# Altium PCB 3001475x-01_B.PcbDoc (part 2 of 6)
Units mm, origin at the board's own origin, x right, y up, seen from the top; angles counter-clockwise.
Board outline 335 x 91 mm, 12 copper layers (Top Layer, L2 GND, Layer 3, L4 GND, Layer 5, L6 PWR, L7 3V3, Layer 8, L9 GND, Layer 10, L11 GND, Bottom Layer), stack 1.59 mm thick; 339 components, 431 nets, 1732 pads, 1526 vias.
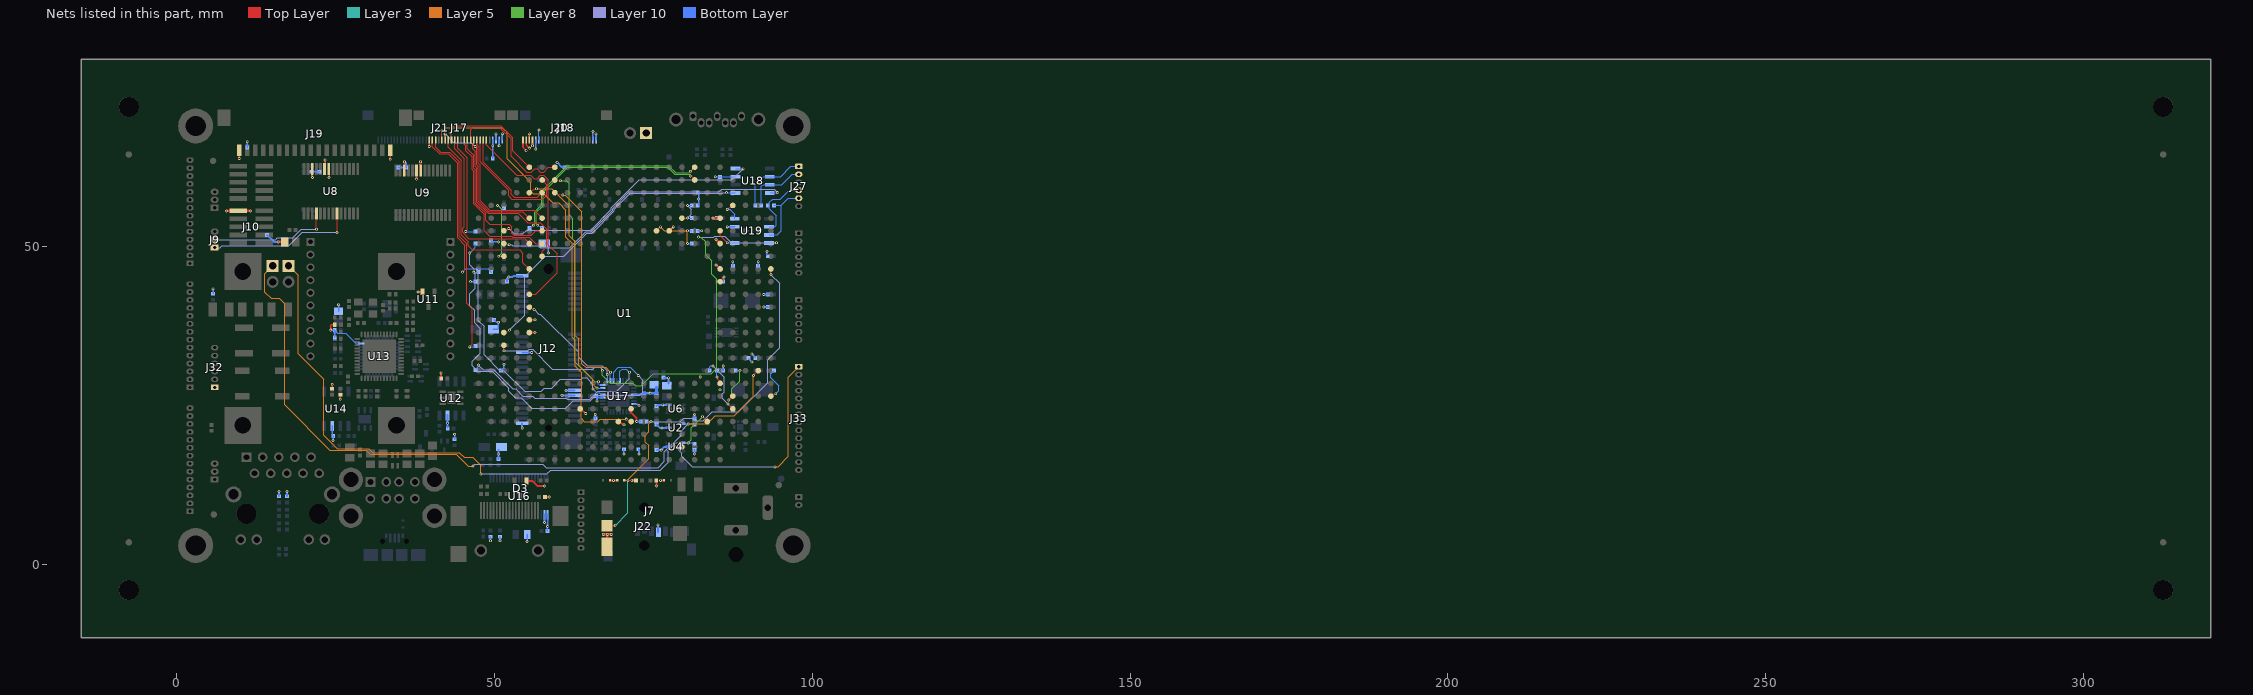
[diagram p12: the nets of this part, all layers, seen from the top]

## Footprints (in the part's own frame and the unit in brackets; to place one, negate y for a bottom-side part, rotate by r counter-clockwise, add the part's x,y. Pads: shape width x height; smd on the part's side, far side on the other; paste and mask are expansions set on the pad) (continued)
MODULE_CCWMX6 [mil]
  round 35 smd: A5(-590.55,905.51) A6(-511.81,905.51) A7(-433.07,905.51) A8(-354.33,905.51) A9(-275.59,905.51) A10(-196.85,905.51) A11(-118.11,905.51) A12(-39.37,905.51) A13(39.37,905.51) A14(118.11,905.51) A15(196.85,905.51) A16(275.59,905.51) A17(354.33,905.51) A18(433.07,905.51) A19(511.81,905.51) A20(590.55,905.51) AA2(-826.77,-669.29) AA3(-748.03,-669.29) AA4(-669.29,-669.29) AA5(-590.55,-669.29) AA6(-511.81,-669.29) AA7(-433.07,-669.29) AA8(-354.33,-669.29) AA9(-275.59,-669.29) AA10(-196.85,-669.29) AA11(-118.11,-669.29) AA12(-39.37,-669.29) AA13(39.37,-669.29) AA14(118.11,-669.29) AA15(196.85,-669.29) AA16(275.59,-669.29) AA17(354.33,-669.29) AA18(433.07,-669.29) AA19(511.81,-669.29) AA20(590.55,-669.29) AA21(669.29,-669.29) AA22(748.03,-669.29) AA23(826.77,-669.29) AB3(-748.03,-748.03) AB4(-669.29,-748.03) AB5(-590.55,-748.03) AB6(-511.81,-748.03) AB7(-433.07,-748.03) AB8(-354.33,-748.03) AB9(-275.59,-748.03) AB10(-196.85,-748.03) AB11(-118.11,-748.03) AB12(-39.37,-748.03) AB13(39.37,-748.03) AB14(118.11,-748.03) AB15(196.85,-748.03) AB16(275.59,-748.03) AB17(354.33,-748.03) AB18(433.07,-748.03) AB19(511.81,-748.03) AB20(590.55,-748.03) AB21(669.29,-748.03) AB22(748.03,-748.03) AC4(-669.29,-826.77) AC5(-590.55,-826.77) AC6(-511.81,-826.77) AC7(-433.07,-826.77) AC8(-354.33,-826.77) AC9(-275.59,-826.77) AC10(-196.85,-826.77) AC11(-118.11,-826.77) AC12(-39.37,-826.77) AC13(39.37,-826.77) AC14(118.11,-826.77) AC15(196.85,-826.77) AC16(275.59,-826.77) AC17(354.33,-826.77) AC18(433.07,-826.77) AC19(511.81,-826.77) AC20(590.55,-826.77) AC21(669.29,-826.77) AD5(-590.55,-905.51) AD6(-511.81,-905.51) AD7(-433.07,-905.51) AD8(-354.33,-905.51) AD9(-275.59,-905.51) AD10(-196.85,-905.51) AD11(-118.11,-905.51) AD12(-39.37,-905.51) AD13(39.37,-905.51) AD14(118.11,-905.51) AD15(196.85,-905.51) AD16(275.59,-905.51) AD17(354.33,-905.51) AD18(433.07,-905.51) AD19(511.81,-905.51) AD20(590.55,-905.51) B4(-669.29,826.77) B5(-590.55,826.77) B6(-511.81,826.77) B7(-433.07,826.77) B8(-354.33,826.77) B9(-275.59,826.77) B10(-196.85,826.77) B11(-118.11,826.77) B12(-39.37,826.77) B13(39.37,826.77) B14(118.11,826.77) B15(196.85,826.77) B16(275.59,826.77) B17(354.33,826.77) B18(433.07,826.77) B19(511.81,826.77) B20(590.55,826.77) B21(669.29,826.77) C3(-748.03,748.03) C4(-669.29,748.03) C5(-590.55,748.03) C6(-511.81,748.03) C7(-433.07,748.03) C8(-354.33,748.03) C9(-275.59,748.03) C10(-196.85,748.03) C11(-118.11,748.03) C12(-39.37,748.03) C13(39.37,748.03) C14(118.11,748.03) C15(196.85,748.03) C16(275.59,748.03) C17(354.33,748.03) C18(433.07,748.03) C19(511.81,748.03) C20(590.55,748.03) C21(669.29,748.03) C22(748.03,748.03) D2(-826.77,669.29) D3(-748.03,669.29) D4(-669.29,669.29) D5(-590.55,669.29) D6(-511.81,669.29) D7(-433.07,669.29) D8(-354.33,669.29) D9(-275.59,669.29) D10(-196.85,669.29) D11(-118.11,669.29) D12(-39.37,669.29) D13(39.37,669.29) D14(118.11,669.29) D15(196.85,669.29) D16(275.59,669.29) D17(354.33,669.29) D18(433.07,669.29) D19(511.81,669.29) D20(590.55,669.29) D21(669.29,669.29) D22(748.03,669.29) D23(826.77,669.29) E1(-905.51,590.55) E2(-826.77,590.55) E3(-748.03,590.55) E4(-669.29,590.55) E5(-590.55,590.55) E6(-511.81,590.55) E7(-433.07,590.55) E8(-354.33,590.55) E9(-275.59,590.55) E10(-196.85,590.55) E11(-118.11,590.55) E12(-39.37,590.55) E13(39.37,590.55) E14(118.11,590.55) E15(196.85,590.55) E16(275.59,590.55) E17(354.33,590.55) E18(433.07,590.55) E19(511.81,590.55) E20(590.55,590.55) E21(669.29,590.55) E22(748.03,590.55) E23(826.77,590.55) E24(905.51,590.55) F1(-905.51,511.81) F2(-826.77,511.81) F3(-748.03,511.81) F4(-669.29,511.81) F5(-590.55,511.81) F6(-511.81,511.81) F7(-433.07,511.81) F8(-354.33,511.81) F9(-275.59,511.81) F10(-196.85,511.81) F11(-118.11,511.81) F12(-39.37,511.81) F13(39.37,511.81) F14(118.11,511.81) F15(196.85,511.81) F16(275.59,511.81) F17(354.33,511.81) F18(433.07,511.81) F19(511.81,511.81) F20(590.55,511.81) F21(669.29,511.81) F22(748.03,511.81) F23(826.77,511.81) F24(905.51,511.81) G1(-905.51,433.07) G2(-826.77,433.07) G3(-748.03,433.07) G4(-669.29,433.07) G5(-590.55,433.07) G6(-511.81,433.07) G7(-433.07,433.07) G8(-354.33,433.07) G9(-275.59,433.07) G10(-196.85,433.07) G11(-118.11,433.07) G12(-39.37,433.07) G13(39.37,433.07) G14(118.11,433.07) G15(196.85,433.07) G16(275.59,433.07) G17(354.33,433.07) G18(433.07,433.07) G19(511.81,433.07) G20(590.55,433.07) G21(669.29,433.07) G22(748.03,433.07) G23(826.77,433.07) G24(905.51,433.07) H1(-905.51,354.33) H2(-826.77,354.33) H3(-748.03,354.33) H4(-669.29,354.33) H5(-590.55,354.33) H6(-511.81,354.33) H19(511.81,354.33) H20(590.55,354.33) H21(669.29,354.33) H22(748.03,354.33) H23(826.77,354.33) H24(905.51,354.33) J1(-905.51,275.59) J2(-826.77,275.59) J3(-748.03,275.59) J4(-669.29,275.59) J5(-590.55,275.59) J20(590.55,275.59) J21(669.29,275.59) J22(748.03,275.59) J23(826.77,275.59) J24(905.51,275.59) K1(-905.51,196.85) K2(-826.77,196.85) K3(-748.03,196.85) K4(-669.29,196.85) K5(-590.55,196.85) K20(590.55,196.85) K21(669.29,196.85) K22(748.03,196.85) K23(826.77,196.85) K24(905.51,196.85) L1(-905.51,118.11) L2(-826.77,118.11) L3(-748.03,118.11) L4(-669.29,118.11) L5(-590.55,118.11) L20(590.55,118.11) L21(669.29,118.11) L22(748.03,118.11) L23(826.77,118.11) L24(905.51,118.11) M1(-905.51,39.37) M2(-826.77,39.37) M3(-748.03,39.37) M4(-669.29,39.37) M5(-590.55,39.37) M20(590.55,39.37) M21(669.29,39.37) M22(748.03,39.37) M23(826.77,39.37) M24(905.51,39.37) N1(-905.51,-39.37) N2(-826.77,-39.37) N3(-748.03,-39.37) N4(-669.29,-39.37) N5(-590.55,-39.37) N20(590.55,-39.37) N21(669.29,-39.37) N22(748.03,-39.37) N23(826.77,-39.37) N24(905.51,-39.37) P1(-905.51,-118.11) P2(-826.77,-118.11) P3(-748.03,-118.11) P4(-669.29,-118.11) P5(-590.55,-118.11) P20(590.55,-118.11) P21(669.29,-118.11) P22(748.03,-118.11) P23(826.77,-118.11) P24(905.51,-118.11) R1(-905.51,-196.85) R2(-826.77,-196.85) R3(-748.03,-196.85) R4(-669.29,-196.85) R5(-590.55,-196.85) R20(590.55,-196.85) R21(669.29,-196.85) R22(748.03,-196.85) R23(826.77,-196.85) R24(905.51,-196.85) T1(-905.51,-275.59) T2(-826.77,-275.59) T3(-748.03,-275.59) T4(-669.29,-275.59) T5(-590.55,-275.59) T20(590.55,-275.59) T21(669.29,-275.59) T22(748.03,-275.59) T23(826.77,-275.59) T24(905.51,-275.59) U1(-905.51,-354.33) U2(-826.77,-354.33) U3(-748.03,-354.33) U4(-669.29,-354.33) U5(-590.55,-354.33) U6(-511.81,-354.33) U19(511.81,-354.33) U20(590.55,-354.33) U21(669.29,-354.33) U22(748.03,-354.33) U23(826.77,-354.33) U24(905.51,-354.33) V1(-905.51,-433.07) V2(-826.77,-433.07) V3(-748.03,-433.07) V4(-669.29,-433.07) V5(-590.55,-433.07) V6(-511.81,-433.07) V7(-433.07,-433.07) V8(-354.33,-433.07) V9(-275.59,-433.07) V10(-196.85,-433.07) V11(-118.11,-433.07) V12(-39.37,-433.07) V13(39.37,-433.07) V14(118.11,-433.07) V15(196.85,-433.07) V16(275.59,-433.07) V17(354.33,-433.07) V18(433.07,-433.07) V19(511.81,-433.07) V20(590.55,-433.07) V21(669.29,-433.07) V22(748.03,-433.07) V23(826.77,-433.07) V24(905.51,-433.07) W1(-905.51,-511.81) W2(-826.77,-511.81) W3(-748.03,-511.81) W4(-669.29,-511.81) W5(-590.55,-511.81) W6(-511.81,-511.81) W7(-433.07,-511.81) W8(-354.33,-511.81) W9(-275.59,-511.81) W10(-196.85,-511.81) W11(-118.11,-511.81) W12(-39.37,-511.81) W13(39.37,-511.81) W14(118.11,-511.81) W15(196.85,-511.81) W16(275.59,-511.81) W17(354.33,-511.81) W18(433.07,-511.81) W19(511.81,-511.81) W20(590.55,-511.81) W21(669.29,-511.81) W22(748.03,-511.81) W23(826.77,-511.81) W24(905.51,-511.81) Y1(-905.51,-590.55) Y2(-826.77,-590.55) Y3(-748.03,-590.55) Y4(-669.29,-590.55) Y5(-590.55,-590.55) Y6(-511.81,-590.55) Y7(-433.07,-590.55) Y8(-354.33,-590.55) Y9(-275.59,-590.55) Y10(-196.85,-590.55) Y11(-118.11,-590.55) Y12(-39.37,-590.55) Y13(39.37,-590.55) Y14(118.11,-590.55) Y15(196.85,-590.55) Y16(275.59,-590.55) Y17(354.33,-590.55) Y18(433.07,-590.55) Y19(511.81,-590.55) Y20(590.55,-590.55) Y21(669.29,-590.55) Y22(748.03,-590.55) Y23(826.77,-590.55) Y24(905.51,-590.55)
  body extent -984,-984 984,984, height 220
MOLEX_53047-0210 [mm]
  rrect20% 0.875x1.125 hole 0.5: 1(0,0)
  oval 0.875x1.15 hole 0.5: 2(1.25,0)
  body extent -1.52,-1.15 2.73,2.05, height 4.2
MOLEX_53047-0310 [mm]
  rect 1x1.25 hole 0.5: 1(0,0)
  oval 1x1.25 hole 0.5: 2(1.25,0) 3(2.5,0)
  body extent -1.5,-1.15 4,2.05, height 4.2
MOLEX_53047-0610#1 [mm]
  rrect20% 0.875x1.125 hole 0.5: 1(0,0)
  oval 0.875x1.15 hole 0.5: 2(1.25,0) 3(2.5,0) 4(3.75,0) 5(5,0) 6(6.25,0)
  body extent -1.5,-1.15 7.75,2.05, height 4.2
MOLEX_53047-0610#2 [mm]
  rect 0.875x1.15 hole 0.5: 1(0,0)
  oval 0.875x1.15 hole 0.5: 2(1.25,0) 3(2.5,0) 4(3.75,0) 5(5,0) 6(6.25,0)
  body extent -1.5,-1.15 7.75,2.05, height 4.2
MOLEX_53047-0810 [mm]
  rect 0.875x1.15 hole 0.5: 1(0,0)
  oval 0.875x1.15 hole 0.5: 2(1.25,0) 3(2.5,0) 4(3.75,0) 5(5,0) 6(6.25,0) 7(7.5,0) 8(8.75,0)
  body extent -1.5,-1.15 10.25,2.05, height 4.2
MOLEX_53047-1410 [mm]
  rrect20% 0.875x1.125 hole 0.5: 1(0,0)
  oval 0.875x1.15 hole 0.5: 2(1.25,0) 3(2.5,0) 4(3.75,0) 5(5,0) 6(6.25,0) 7(7.5,0) 8(8.75,0) 9(10,0) 10(11.25,0) 11(12.5,0) 12(13.75,0) 13(15,0) 14(16.25,0)
  body extent -1.5,-1.15 17.75,2.05, height 4.2
MOLEX_78727-0001 [mm]
  rect 0.8x0.6 smd: 1(0.33,4.38) 2(0.33,1.84) 3(0.33,-0.7) 4(0.33,-3.24) 5(-7.29,4.38) 6(-7.29,1.84) 7(-7.29,-0.7) 8(-7.29,-3.24)
  rect 0.85x0.8 smd: 9(-13.99,-4.98)
  rect 1.5x0.42 smd: 10(-2.47,-6.54) 12(-6.35,7.11) 13(-12.21,7.11) 14(-12.21,-7.11) 15(-6.35,-7.11)
  rect 1.4x0.87 smd: 11(0,6.95) 16(0,-6.95)
  body extent -14.53,-7.26 0.69,7.27, height 1.4
MOLEX_500873-0806 [mm]
  rect 0.8x1.5 smd: 1(0,0) 2(1.1,-0.4) 3(2.2,0) 4(3.3,0.2) 5(4.4,0) 6(5.5,0.2) 7(6.6,0) 8(7.7,0)
  rect 1.8x1.4 smd: 9(1.2,-10.3) 10(6.9,-10.3)
  rect 1.4x1.9 smd: 11(8.5,2.85) 12(-4.65,3.85)
  Top Layer keep-out region: 8.6,1.75 9.2,1.75 9.2,-11 8.6,-11
  body extent -5.05,-10.7 8.95,4.5, height 1.87
omron_xf2m-2015-1a [mm]
  rect 0.25x1.1 smd: 1(-4.75,1.95) 2(-4.25,1.95) 3(-3.75,1.95) 4(-3.25,1.95) 5(-2.75,1.95) 6(-2.25,1.95) 7(-1.75,1.95) 8(-1.25,1.95) 9(-0.75,1.95) 10(-0.25,1.95) 11(0.25,1.95) 12(0.75,1.95) 13(1.25,1.95) 14(1.75,1.95) 15(2.25,1.95) 16(2.75,1.95) 17(3.25,1.95) 18(3.75,1.95) 19(4.25,1.95) 20(4.75,1.95)
  rect 1.7x1.5 smd: M1(6.4,-1.95) M2(-6.4,-1.95)
  body extent -7.05,-2.9 7.05,3.3, height 2.18
OMRON_XF2M-2415-1A [mm]
  rect 0.25x1.1 smd: 1(-5.75,1.95) 2(-5.25,1.95) 3(-4.75,1.95) 4(-4.25,1.95) 5(-3.75,1.95) 6(-3.25,1.95) 7(-2.75,1.95) 8(-2.25,1.95) 9(-1.75,1.95) 10(-1.25,1.95) 11(-0.75,1.95) 12(-0.25,1.95) 13(0.25,1.95) 14(0.75,1.95) 15(1.25,1.95) 16(1.75,1.95) 17(2.25,1.95) 18(2.75,1.95) 19(3.25,1.95) 20(3.75,1.95) 21(4.25,1.95) 22(4.75,1.95) 23(5.25,1.95) 24(5.75,1.95)
  rect 1.7x1.5 smd: M1(7.4,-1.95) M2(-7.4,-1.95)
  body extent -8.05,-3.55 8.05,2.65, height 3.2
OMRON_XF2M-4015-1A [mm]
  rect 0.25x1.1 smd: 1(-9.75,1.95) 2(-9.25,1.95) 3(-8.75,1.95) 4(-8.25,1.95) 5(-7.75,1.95) 6(-7.25,1.95) 7(-6.75,1.95) 8(-6.25,1.95) 9(-5.75,1.95) 10(-5.25,1.95) 11(-4.75,1.95) 12(-4.25,1.95) 13(-3.75,1.95) 14(-3.25,1.95) 15(-2.75,1.95) 16(-2.25,1.95) 17(-1.75,1.95) 18(-1.25,1.95) 19(-0.75,1.95) 20(-0.25,1.95) 21(0.25,1.95) 22(0.75,1.95) 23(1.25,1.95) 24(1.75,1.95) 25(2.25,1.95) 26(2.75,1.95) 27(3.25,1.95) 28(3.75,1.95) 29(4.25,1.95) 30(4.75,1.95) 31(5.25,1.95) 32(5.75,1.95) 33(6.25,1.95) 34(6.75,1.95) 35(7.25,1.95) 36(7.75,1.95) 37(8.25,1.95) 38(8.75,1.95) 39(9.25,1.95) 40(9.75,1.95)
  rect 1.7x1.5 smd: M1(11.4,-1.95) M2(-11.4,-1.95)
  body extent -12.05,-2.9 12.05,3.3, height 2.18
OSC210P320X250X90-4N [mm]
  rect 1.3x1.1 smd: 1(-1.15,-0.95) 2(1.15,-0.95) 3(1.15,0.95) 4(-1.15,0.95)
  body extent -1.63,-1.3 1.62,1.3, height 0.6
QFN50P500X500X100-33CN [mm]
  rrect50% 0.85x0.3 smd: 1(-2.45,1.75) 2(-2.45,1.25) 3(-2.45,0.75) 4(-2.45,0.25) 5(-2.45,-0.25) 6(-2.45,-0.75) 7(-2.45,-1.25) 8(-2.45,-1.75) 17(2.45,-1.75) 18(2.45,-1.25) 19(2.45,-0.75) 20(2.45,-0.25) 21(2.45,0.25) 22(2.45,0.75) 23(2.45,1.25) 24(2.45,1.75)
  rrect50% 0.3x0.85 smd: 9(-1.75,-2.45) 10(-1.25,-2.45) 11(-0.75,-2.45) 12(-0.25,-2.45) 13(0.25,-2.45) 14(0.75,-2.45) 15(1.25,-2.45) 16(1.75,-2.45) 25(1.75,2.45) 26(1.25,2.45) 27(0.75,2.45) 28(0.25,2.45) 29(-0.25,2.45) 30(-0.75,2.45) 31(-1.25,2.45) 32(-1.75,2.45)
  rect 3.45x3.45 smd: 33(0,0)
  body extent -2.5,-2.5 2.5,2.5, height 1.01
QFN50P600X600X100-37AN [mm]
  rrect35% 1.05x0.3 smd: 1(-2.8,2) 9(-2.8,-2) 19(2.8,-2) 27(2.8,2)
  rrect25% 1.1x0.3 smd: 2(-2.8,1.5) 3(-2.8,1) 4(-2.8,0.5) 5(-2.8,0) 6(-2.8,-0.5) 7(-2.8,-1) 8(-2.8,-1.5) 20(2.8,-1.5) 21(2.8,-1) 22(2.8,-0.5) 23(2.8,0) 24(2.8,0.5) 25(2.8,1) 26(2.8,1.5)
  rrect35% 0.3x1.05 smd: 10(-2,-2.8) 18(2,-2.8) 28(2,2.8) 36(-2,2.8)
  rrect25% 0.3x1.1 smd: 11(-1.5,-2.8) 12(-1,-2.8) 13(-0.5,-2.8) 14(0,-2.8) 15(0.5,-2.8) 16(1,-2.8) 17(1.5,-2.8) 29(1.5,2.8) 30(1,2.8) 31(0.5,2.8) 32(0,2.8) 33(-0.5,2.8) 34(-1,2.8) 35(-1.5,2.8)
  rect 3.8x3.8 smd: 37(0,0)
  body extent -3.05,-3.05 3.05,3.05, height 1.01
QFN50P700X700X100-49N [mm]
  oval 0.9x0.3 smd: 1(-3.45,2.75) 2(-3.45,2.25) 3(-3.45,1.75) 4(-3.45,1.25) 5(-3.45,0.75) 6(-3.45,0.25) 7(-3.45,-0.25) 8(-3.45,-0.75) 9(-3.45,-1.25) 10(-3.45,-1.75) 11(-3.45,-2.25) 12(-3.45,-2.75) 25(3.45,-2.75) 26(3.45,-2.25) 27(3.45,-1.75) 28(3.45,-1.25) 29(3.45,-0.75) 30(3.45,-0.25) 31(3.45,0.25) 32(3.45,0.75) 33(3.45,1.25) 34(3.45,1.75) 35(3.45,2.25) 36(3.45,2.75)
  oval 0.3x0.9 smd: 13(-2.75,-3.45) 14(-2.25,-3.45) 15(-1.75,-3.45) 16(-1.25,-3.45) 17(-0.75,-3.45) 18(-0.25,-3.45) 19(0.25,-3.45) 20(0.75,-3.45) 21(1.25,-3.45) 22(1.75,-3.45) 23(2.25,-3.45) 24(2.75,-3.45) 37(2.75,3.45) 38(2.25,3.45) 39(1.75,3.45) 40(1.25,3.45) 41(0.75,3.45) 42(0.25,3.45) 43(-0.25,3.45) 44(-0.75,3.45) 45(-1.25,3.45) 46(-1.75,3.45) 47(-2.25,3.45) 48(-2.75,3.45)
  rect 5.3x5.3 smd: 49(0,0)
  body extent -3.57,-3.57 3.57,3.57, height 1.01
RESC1005X40N [mm]
  rect 0.57x0.62 smd: 1(-0.48,0) 2(0.48,0)
  body extent -0.5,-0.25 0.5,0.25, height 0.4
RESC1609X55N [mm]
  rect 0.9x1 smd: 1(-0.8,0) 2(0.8,0)
  body extent -0.87,-0.48 0.87,0.48, height 0.55
SAMTEC_FTSH-105-01-F-DV [mil]
  rect 110x29 smd: 1(-80,100) 2(80,100) 3(-80,50) 4(80,50) 5(-80,0) 6(80,0) 7(-80,-50) 8(80,-50) 9(-80,-100) 10(80,-100)
  body extent -115,-125 115,125, height 234
SAMTEC_MMS-110-01-L-SV [mil]
  rect 50x50 hole 28: 1(0,0)
  round 50 hole 28: 2(78.74,0) 3(157.48,0) 4(236.22,0) 5(314.96,0) 6(393.7,0) 7(472.44,0) 8(551.18,0) 9(629.92,0) 10(708.66,0)
  body extent -44,-39 753,39, height 175
SODFL1006X43N12 [mm]
  rect 0.32x0.43 smd: 1(-0.55,0) 2(0.55,0)
  body extent -0.58,-0.33 0.58,0.33, height 0.4
SOIC127P600X175-8N [mm]
  rect 0.6x1.55 smd: 1(-1.905,-2.7) 2(-0.635,-2.7) 3(0.635,-2.7) 4(1.905,-2.7) 5(1.905,2.7) 6(0.635,2.7) 7(-0.635,2.7) 8(-1.905,2.7)
  body extent -2.5,-3.1 2.5,3.1, height 1.75
SON45P300X200X80_175X145E-9AN [mm] "DFN8 with D shape pads - 1.75mm x 1.45mm E-pad"
  rrect100% 0.8x0.25 smd paste-0.03: 1(-1.5,0.675) 2(-1.5,0.225) 3(-1.5,-0.225) 4(-1.5,-0.675) 5(1.5,-0.675) 6(1.5,-0.225) 7(1.5,0.225) 8(1.5,0.675)
  rect 1.75x1.45 smd: 9(0,0)
  body extent -1.5,-1 1.5,1, height 0.8
SON95P300X300X80-7N [mm]
  rect 0.4x1 smd: 1(-0.95,-1.4) 2(0,-1.4) 3(0.95,-1.4) 4(0.95,1.4) 5(0,1.4) 6(-0.95,1.4)
  rect 2x1.3 smd: 7(0,0)
  body extent -1.58,-1.58 1.58,1.58, height 0.8
SOP50P640X120-38N [mm]
  rect 1.5x0.3 smd: 1(-2.9,4.5) 2(-2.9,4) 3(-2.9,3.5) 4(-2.9,3) 5(-2.9,2.5) 6(-2.9,2) 7(-2.9,1.5) 8(-2.9,1) 9(-2.9,0.5) 10(-2.9,0) 11(-2.9,-0.5) 12(-2.9,-1) 13(-2.9,-1.5) 14(-2.9,-2) 15(-2.9,-2.5) 16(-2.9,-3) 17(-2.9,-3.5) 18(-2.9,-4) 19(-2.9,-4.5) 20(2.9,-4.5) 21(2.9,-4) 22(2.9,-3.5) 23(2.9,-3) 24(2.9,-2.5) 25(2.9,-2) 26(2.9,-1.5) 27(2.9,-1) 28(2.9,-0.5) 29(2.9,0) 30(2.9,0.5) 31(2.9,1) 32(2.9,1.5) 33(2.9,2) 34(2.9,2.5) 35(2.9,3) 36(2.9,3.5) 37(2.9,4) 38(2.9,4.5)
  body extent -3.3,-4.9 3.3,4.9, height 1.1
SOP65P780X200-28N [mm] "28-LEAD SHRINK SMALL OUTLINE  PACKAGE"
  rect 1.9x0.45 smd: 1(-3.5,4.225) 2(-3.5,3.575) 3(-3.5,2.925) 4(-3.5,2.275) 5(-3.5,1.625) 6(-3.5,0.975) 7(-3.5,0.325) 8(-3.5,-0.325) 9(-3.5,-0.975) 10(-3.5,-1.625) 11(-3.5,-2.275) 12(-3.5,-2.925) 13(-3.5,-3.575) 14(-3.5,-4.225) 15(3.5,-4.225) 16(3.5,-3.575) 17(3.5,-2.925) 18(3.5,-2.275) 19(3.5,-1.625) 20(3.5,-0.975) 21(3.5,-0.325) 22(3.5,0.325) 23(3.5,0.975) 24(3.5,1.625) 25(3.5,2.275) 26(3.5,2.925) 27(3.5,3.575) 28(3.5,4.225)
  body extent -4.1,-5.25 4.1,5.25, height 2.01
SOT65P210X110-5N [mm]
  rect 0.4x0.95 smd: 1(-0.65,-1.1) 2(0,-1.1) 3(0.65,-1.1) 4(0.65,1.1) 5(-0.65,1.1)
  body extent -1.07,-1.2 1.07,1.2, height 1.11
SOT65P210X110-6N [mm]
  rect 0.4x0.95 smd: 1(-0.65,-1.1) 2(0,-1.1) 3(0.65,-1.1) 4(0.65,1.1) 5(0,1.1) 6(-0.65,1.1)
  body extent -1.07,-1.2 1.07,1.2, height 1.11
SOT95P240X110-3N [mm]
  rect 0.7x1.1 smd: 1(-0.95,-1.2) 2(0.95,-1.2) 3(0,1.2)
  body extent -1.56,-1.35 1.56,1.35, height 1.11
SOT95P240X110_AXK-3N [mm]
  rect 0.65x1.05 smd: A(-0.95,-1.15) K(0,1.15) X(0.95,-1.15)
  body extent -1.56,-1.35 1.56,1.35, height 1.11
SOT95P240X110_GSD-3N [mm]
  rect 0.65x1.05 smd: D(0,1.15) G(-0.95,-1.15) S(0.95,-1.15)
  body extent -1.56,-1.35 1.56,1.35, height 1.11
SOTFL50P160X80_GSD-3N [mm]
  rect 0.4x0.77 smd: D(0,0.69) G(-0.5,-0.69) S(0.5,-0.69)
  body extent -0.85,-0.85 0.85,0.85, height 0.8
SW_KSC221J [mm]
  rect 1x2.8 smd: 1(2,2.9) 2(2,-2.9) 3(-2,2.9) 4(-2,-2.9)
  body extent -3.1,-3.4 3.1,3.4, height 3.5
XTAL_C3E-3427 [mm]
  rect 1.4x1.15 smd: 1(-1.1,-0.8) 2(1.1,-0.8) 3(1.1,0.8) 4(-1.1,0.8)
  body extent -1.7,-1.35 1.7,1.35, height 0.75

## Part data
C1 C34 C35 C36: library part 1001196, "CAP TANT 100UF 6.3V 20% 1206"
C2 C9 C11 C12 C42 C49 C56 C57 C60 C67 C69 C71 C72 C98: library part 1001168, "CAP CER 10UF 10V 20% X5R 0402"
C3 C18 C19 C20 C21 C22 C23 C24 C25 C26 C27 C62 C65 C87 C88 C91 C92 C93 C94: library part 1001167, "CAP CER 1UF 10V 10% X5R 0402"
C4 C5 C6 C7 C10 C13 C29 C31 C32 C33 C37 C38 C39 C41 C43 C44 C45 C46 C47 C48 C50 C51 C52 C53 C54 C55 C58 C59 C61 C66 C68 C70 C73 C74 C75 C76 C77 C78 C79 C81 C82 C83 C84 C85 C86 C89 C90 C95 C96 C97 C99 C100 C101: library part 1000006, "CAP 100nF 16V 10% X7R 0402"
C8: library part 1001164, "CAP TANT 47UF 20V 10% 2413"
C14 C15 C16 C17: library part 1001165, "CAP CER 10000PF 16V 10% X7R 0402"
C28 C30: library part 1001166, "CAP CER 22PF 50V 5% NP0 0402"
C40 C80: library part 1000500, "CAP CER 4.7UF 25V 10% X5R 0805"
C63 C64: library part 1000010, "CAP 33pF 50V 5% NP0 0402"
D1 D4: library part 1001189, "LED GREEN 573NM 1208 SMD"
D2: library part 1000824, "DIODE ZENER 5.1V 300MW SOT23-3"
D3: library part 1001169, "DIODE SCHOTTKY 30V 0.2A SOT23-3"
D5: library part 1001188, "LED YELLOW 588NM 1208 SMD"
D6: library part 1001190, "LED RED 653NM 20MA 1208 SMD"
D7 D8 D9 D10: library part 1001264, "TVS DIODE 5VWM SOD923"
FIDUCIAL1 FIDUCIAL2 FIDUCIAL3 FIDUCIAL4 FIDUCIAL5 FIDUCIAL6: library part CAD0023, "40 Mil Round Fiducial"
H1048 H1049 H1050 H1051: library part CAD0006
H1052 H1053 H1054 H1055: library part CAD0023
J1: library part 1001105, "DC Power Jack"
J2: library part 1001136, "CONN HEADER 2POS 1.25MM VERT TIN"
J3 J9 J25: library part 1001183, "CONN HEADER 3POS 1.25MM VERT TIN"
J4 J5: library part 1001128, "CONN HEADER 2POS .100\" SGL GOLD"
J6: library part 1001106, "CONN HEADER 2POS .100 VERT GOLD"
J7: library part 1001118, "CONN TRANSFLSH R/A PUSH-PUSH SMD"
J8: library part 1001115, "CONN PLUG SATA 7PS VERT PCB GOLD"
J10 J11: library part 1000034, "CONN HEADER 10POS DUAL .05\" SMD"
J12: library part 1001130, "SMCONN,MINI PCI EXP, 6.8MM HT"
J13: library part 1001142, "CONN MAGJACK 1PORT 1000 BASE-T"
J14: library part 1001120, "MEMORY CARD 6POS PUSH/PULL SMD"
J15: library part 1001121, "USB Stacked Dual A type"
J16: library part 1001117, "CONN RECEPT MICRO-USB TYPE AB R/A"
J17 J18: library part 1001145, "CONN FPC 20POS 0.5MM PITCH SMD"
J19: library part 1001132, "CONN HEADER 20POS 1.25MM R/A SMD"
J20: library part 1001182, "CONN FPC 24POS 0.5MM PITCH SMD"
J21: library part 1001144, "CONN FPC 40POS 0.5MM PITCH SMD"
J22: library part 1001133, "CONN JACK STEREO 5POS 3.5MM SMD"
J23 J24: library part 1001131, "CONN RCPT 2MM 10POS SGL VERT PCB"
J26: library part 1001139, "CONN HEADER 8POS 1.25MM VERT TIN"
J27 J28 J32 J34: library part 1001138, "CONN HEADER 6POS 1.25MM VERT TIN"
J29 J30 J31 J33: library part 1001140, "CONN HEADER 14POS 1.25MM STR TIN"
L1: library part 1001172, "INDUCTOR POWER 4.7UH 1.7A SMD"
L2 L3 L4 L5 L18 L19 L20 L21 L22 L23 L24 L25: library part 1001175, "FERRITE BEAD 120 OHM .35A 0402"
L6 L7 L9 L12 L13 L15 L17 L26 L27 L28: library part 1001174, "FERRITE BEAD 220 OHM 2.0A 0805"
L8 L10 L11 L14 L16: library part 1001173, "CHOKE COM MODE 120 OHM .37A"
P1: library part 1001123, "HDMI RECEPTACLE, SMT"
Q1: library part 1001204, "TRANS GP SS PNP 40V SOT23"
Q2: library part 1000715, "MOSFET N-CH 60V 115MA SOT-523F"
R1 R2 R3 R42 R43: library part 1000466, "RES 49.9 OHM 1/10W 1% 0402 SMD"
R4 R5 R6 R20 R21 R24 R25 R44 R47 R51 R52 R79 R80 R81 R82 R83 R84 R95 R96 R97 R98 R99 R100 R101 R102 R103 R105 R106 R107 R108 R111 R112 R113 R114 R115 R123 R124: library part 1000076, "RES 0.0 OHM 1/10W 0402 SMD"
R7 R13 R28 R29 R31 R32 R33 R34 R36 R53 R55 R58 R60 R61 R62 R63 R64 R65 R66 R69 R72 R76 R77 R78 R91 R92 R93 R117 R118 R122: library part 1000537, "RES 10.0K OHM 1/10W 1% 0402 SMD"
R8 R35 R46 R48: library part 1000467, "RES 100 OHM 1/10W 1% 0402 SMD"
R9 R10 R16 R17 R18 R19 R22 R41 R50 R54 R56 R57 R59: library part 1000079, "RES 1.00K OHM 1/10W 1% 0402 SMD"
R11: library part 1000178, "RES 270 OHM 1/10W 1% 0402 SMD"
R12 R38 R45: library part 1001154, "RES 220 OHM 1/16W 1% 0402 SMD"
R14: library part 1000701, "RES 470K OHM 1/10W 1% 0402 SMD"
R15 R27: library part 1001150, "RES 316K OHM 1/10W 1% 0603 SMD"
R23 R39 R67: library part 1000971, "RES 1.00M OHM 1/16W 1% 0402 SMD"
R26 R30: library part 1001149, "RES 22.1K OHM 1/16W 1% 0402 SMD"
R37 R40 R75 R85 R87: library part 1000038, "RES 4.7K OHM 1/10W 5% 0402 SMD"
R49 R70: library part 1000828, "RES 12.1K OHM 1/10W 1% 0402 SMD"
R68 R71 R73 R74 R88 R90: library part 1001155, "RES 47.0K OHM 1/16W 1% 0402 SMD"
R86: library part 1001153, "RES 27.0K OHM 1/16W 1% 0402 SMD"
R89: library part 1000174, "RES 15.0K OHM 1/10W 1% 0402 SMD"
R94 R109 R110: library part 1001156, "RES 2.20K OHM 1/16W 1% 0402 SMD"
R104 R116 R119 R120 R121: library part 1001158, "RES 120 OHM 1/16W 1% 0402 SMD"
SW1: library part 1001124, "SWITCH TACTILE SPST-NO 0.05A 32V"
SW2: library part 1001171, "SWITCH TACTILE SPST-NO 0.05A 12V"
U1: library part CCWMX6_LGA400
U2 U4: library part 1001179, "IC SWITCH SPDT SC88"
U3: library part 1001205, "MOSFET P-CH 20V 7.8A 6-MICROFET"
U5: library part 1001206, "TVS DIODE 5VWM 9.2VC SMB"
U6: library part 1001160, "IC GATE NAND 2-INP HS LOG SC70-5"
U7: library part 1001162, "IC REG BOOST SYNC ADJ 1.2A 8DFN"
U8 U9: library part 1001135, "IC TXRX RS232 INTELLIGENT 28SSOP"
U10: library part 1001110, "IC TXRX ETHERNET 48-QFN"
U11 U15: library part 1001163, "MOSFET P-CH 20V 3.7A SOT23-3"
U12 U14: library part 1001143, "IC SW DISTRIBUTION 2CHAN 8SOIC"
U13: library part 1001114, "4-PORT USB 2.0 HUB CTRLR 36VQFN"
U16: library part 1001125, "IC HDMI XMITTER PORT P/I 38TSSOP"
U17: library part 1001126, "IC AUDIO CODEC STEREO 32-QFN"
U18 U19: library part 1001129, "IC CAN TRANSCEIVER 3.3V 8-SOIC"
U20 U21: library part 1001265, "TVS DIODE 5.5VWM 6SON"
X1: library part 1001176, "CRYSTAL 25MHz SMT"
X2: library part 1001134, "CRYSTAL 24MHZ 18PF SMD"

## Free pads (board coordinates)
  round 5.5 hole 3.2: 0(3,3) 0(3,69) 0(97,3) 0(97,69)
  rect 5.8x5.8 hole 2.6: 0(10.45,21.9) 0(10.45,46.1) 0(34.6,21.9) 0(34.6,46.1)

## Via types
v1: diameter 0.45, hole 0.2, Top Layer to Bottom Layer, 1511 vias
v2: diameter 0.5, hole 0.2, Top Layer to Bottom Layer, 14 vias
v3: diameter 0.45/0.45/0.45/0.45/0.45/0.45/0.45/0.45/0.45/0.45/0.45/0.45 (per signal layer), hole 0.2, Top Layer to Bottom Layer, 1 vias

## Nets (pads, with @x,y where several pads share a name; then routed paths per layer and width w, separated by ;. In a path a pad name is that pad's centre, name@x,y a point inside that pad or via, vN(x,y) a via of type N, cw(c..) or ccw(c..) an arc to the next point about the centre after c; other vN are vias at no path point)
3V3: C5.2 C6.2 C7.2 C12.2 C13.2 C19.1 C21.1 C26.1 C27.1 C34.1 C35.1 C36.1 C37.2 C38.2 C39.2 C82.2 C95.2 C96.2 C99.2 C100.2 D3.A J7.4 J10.1 J12.2 J12.24 J12.39 J12.41 J12.52 J17.20 J18.1 J18.2 J19.1 J21.37 J21.38 L2.1 L17.2 L26.1 L28.2 R7.2 R9.2 R10.2 R16.2 R22.2 R24.2 R25.2 R30.2 R31.2 R32.2 R33.2 R34.2 R36.2 R38.2 R45.2 R64.2 R65.2 R66.2 R68.2 R69.1 R75.1 R76.1 R77.1 R78.1 R88.1 R90.1 R93.2 R109.2 R110.2 R117.1 R118.1 R122.1 U1.AA12 U1.E20 U1.G20 U1.J20 U1.K20 U1.N5 U1.P5 U1.Y9 U1.Y13 U2.5 U4.5 U6.5 U8.22 U8.23 U8.26 U9.22 U9.23 U9.26 U11.S U13.27 U16.2 U17.20 U18.3 U19.3 | length 107.8
  Top Layer w0.25: v1(21.375,60.875) U8.26@21.375,62.222 ; U8.23@23.375,62.328 v1(23.375,63.625) ; v1(24,60.875) U8.22@24,62.197 ; v1(24.25,36.875) 24.25,37.625 24.375,37.75 L2.1@24.895,37.75 ; v1(33.625,63.75) J19.1@33.625,65.2 ; v1(38,42.875) U11.S@38.65,42.875 ; v1(39.75,65.75) J17.20@39.75,66.8 ; U1.N5@55.5,38.5 v1(56.375,38.5) ; U1.Y9@63.5,24.5 v1(64.375,23.75)
  Top Layer w0.3: R65.2@24.49,27.68 v1@24.49,28.365 ; v1@25.76,26.01 R66.2@25.76,26.72 ; U9.26@35.875,62.05 v1(35.875,63.375) ; v1(37.75,60.625) U9.23@37.75,61.975 ; U9.22@38.375,62.05 v1(38.375,63.375) ; R64.2@41.625,29.27 v1(41.625,30.125) ; D3.A@55.075,13.15 55.975,13.15 56.75,12.375 v1(57.875,12.375) ; U1.P5@55.5,36.5 v1(56.375,36.5) ; C82.2@57.96,10.625 v1(58.625,10.625) ; U1.AA12@69.5,22.5 v1(70.375,22) ; U1.Y13@71.5,24.5 71.5,23.875 72.375,23 v1(72.375,22.5) ; v1(75.5,12.375) C12.2@75.5,13.21 ; v1(84.875,47.125) U1.J20@85.5,46.5 ; U1.K20@85.5,44.5 v1(86.125,45.25)
  Top Layer w0.4: v1(7.875,55.625) v1(11.625,55.625) ; v1(16,50.75) L28.2@17.025,50.75 ; v1(71.625,13.25) C13.2@72.29,13.25 ; v1(84.375,54.5) U1.E20@85.5,54.5 ; v1(84.875,51.125) U1.G20@85.5,50.5
  Bottom Layer w0.125: R68.2@24.895,36.86 25.377,36.377 26.622,36.377 28.25,34.75 U13.27@29.075,34.75
  Bottom Layer w0.15: J18.2@56.95,66.85 56.95,68.325 v1(57,68.375) ; v1(84.75,61) C99.2@85.54,61 ; C99.2@85.55,61.01 U18.3@87.925,61.01
  Bottom Layer w0.25: R118.1@5.75,42.605 v1@5.75,43.355 ; R76.1@11.125,65.605 v1(11.125,66.5) ; R45.2@16.125,10.73 v1(16.125,11.5) ; R38.2@17.375,10.73 v1(17.375,11.5) ; C19.1@21.25,61.79 C26.1@22.5,61.79 ; v1(21.375,60.875) C19.1@21.375,61.665 ; v1(24.25,36.875) R68.2@24.895,36.875 ; R69.1@24.895,35.75 R68.2@24.895,36.86 ; L17.2@25.5,39.85 v1(25.5,40.875) ; R75.1@43.75,19.73 v1(43.75,20.5) ; v1(46.25,44.5) R122.1@47.02,44.5 ; v1(49.375,3.75) R90.1@49.375,4.395 ; R110.2@49.5,50.98 49.73,50.75 v1(50.625,50.75) ; R78.1@49.75,63.895 v1(49.75,65.875) J21.37@49.75,66.8 ; C35.1@49.85,37 50.625,37 v1(50.625,38.125) 50.335,38.125 C39.2@49.96,38.5 ; J21.38@50.25,66.8 v1(50.25,67.75) ; v1(50.875,3.75) R88.1@50.875,4.395 ; R109.2@51.02,30.5 51.5,30.98 v1(51.5,31.5) ; v1(56.5,65.375) J18.1@56.5,66.8 ; C36.1@57.85,50.5 58.5,50.5 v1(58.5,49) ; R25.2@81.98,52.5 v1(82.625,52.5) ; R24.2@82.125,56.52 v1(82.125,57.5) R36.2@82.125,58.48 ; v1(86.625,53.125) U19.3@87.79,53.125 ; R117.1@92.875,48.645 v1(92.875,49.25)
  Bottom Layer w0.3: R7.2@14.23,51.875 15.355,50.75 v1(16,50.75) ; C21.1@34.875,62.46 C27.1@36.125,62.46 36.125,63.125 v1(35.875,63.375) ; C38.2@50.625,16.585 v1(50.625,17.375) C34.1@50.625,18.025 ; C37.2@51.96,44.5 51.96,44.96 v1(52.25,45.25) 52.875,45.25 53.025,45.4 J12.2@54.4,45.4 ; v1(54.375,21.5) J12.52@54.375,22.175 ; J12.24@54.425,33.375 v1(55.875,33.375) ; v1(57.875,6.625) U16.2@57.875,7.85 ; v1(59.875,63.25) 60.625,62.5 R77.1@61.02,62.5 ; v1(60.625,26.625) J12.41@62.575,26.625 ; v1(61.25,27.375) J12.39@62.575,27.375 ; C95.2@65.96,26.5 C95.2@66.21,26.25 ; v1(66.125,25.75) 66.125,26.25 C95.2@66.21,26.25 ; U17.20@67.05,26.25 C95.2@66.21,26.25 ; v1(72.375,22.5) R93.2@73.02,22.5 ; C6.2@75.5,22.04 76.04,21.5 v1(76.375,21.5) U2.5@77.4,21.5 ; C5.2@75.5,24.96 75.665,25.125 v1(76.5,25.125) U6.5@77.375,25.125 ; C7.2@75.54,18 v1(76.25,18) 76.75,18.5 U4.5@77.4,18.5 ; J7.4@75.75,5.1 v1(75.75,6.25) ; C96.2@76.665,29.375 v1(77.375,29.375) L26.1@77.375,28.475 ; v1(81.5,17.375) R10.2@81.5,18.02 ; R9.2@81.5,22.98 v1(81.5,23.625) ; R16.2@85.98,30.5 v1(86,31.25) ; R30.2@85.98,44.5 85.98,45.105 v1(86.125,45.25) ; R33.2@87.5,46.98 v1(87.5,47.625) ; v1(90.5,33.125) R22.2@91.02,32.605 ; R31.2@91.5,46.98 v1(91.5,47.625) ; v1(92.375,40.5) R34.2@93.02,40.5 ; v1(92.375,42.5) R32.2@93.02,42.5
  Bottom Layer w0.4: v1(84.375,54.5) C100.2@85.04,54.5
  other v1: 25.75,26 85.5,27.5 24.5,28.375 82.375,29.5 5.73,43.375
5V: C62.2 C65.1 C80.2 C81.2 J6.1 J18.19 J18.20 J19.20 J20.21 J20.22 J20.23 J20.24 J21.39 J21.40 J32.1 R21.2 U1.F16 U12.7 U14.7 U16.1 | length 20.2
  Top Layer w0.25: v1(9.875,63.875) J19.20@9.875,65.2 ; J20.24@54.5,66.8 54.5,65.625 v1(55,65.125) ; J20.23@55,66.8 55,66 v1(55.5,65.5) ; J20.22@55.5,66.8 v1(55.5,67.75) ; v1(56,65.875) J20.21@56,66.8 ; U1.F16@77.5,52.5 v1(78.125,53.125)
  Bottom Layer w0.25: C65.1@24.49,20.425 U14.7@24.49,21.8 ; v1(24.625,19.5) C65.1@24.625,20.21 ; C62.2@42.625,21.54 v1(42.625,22.25) U12.7@42.625,23.54 ; v1(50.75,65.875) J21.39@50.75,66.8 ; J21.40@51.25,66.8 v1(51.25,67.75) ; v1@55.15,3.65 C80.2@55.15,4.75 ; C81.2@58.335,5.25 58.335,5.96 v1(58.375,6) ; J18.19@65.5,66.8 v1(65.5,68.125) ; J18.20@66,66.8 v1(66,67.75) ; R21.2@89.98,32.395 v1(90.5,31.875)
  Bottom Layer w0.3: v1(58.375,6) 58.375,6.358 58.4,6.383 58.4,7.825 U16.1@58.375,7.85
  other v1: 55.125,3.625
AGND: C94.1 C97.1 C98.1 D7.1 D8.1 D9.1 J22.1 L27.2 R91.1 R92.1 U17.4 U17.7 | length 13.1
  Top Layer w0.3: D7.1@68.175,13.25 v1(68.75,13.25) D9.1@69.325,13.25 ; v1(76.125,13.25) D8.1@76.7,13.25
  Top Layer w0.4: v1(67.125,4.75) v1(67.75,4.75) ; J22.1@67.7,2.8 J22.1@67.7,3.325 ; J22.1@67.75,2.8 v1(67.75,4.75) ; v1(68.375,4.75) v1(67.75,4.75)
  Bottom Layer w0.25: C94.1@65.875,22.96 v1(65.875,23.625) ; v1(70.375,17.375) R91.1@70.375,18.145 ; U17.7@71.95,25.25 72.5,25.25 v1(72.75,25) ; U17.4@71.95,26.75 73.25,26.75 C97.1@73.46,26.96 ; v1(72.75,17.375) R92.1@72.75,18.145
  Bottom Layer w0.4: C97.1@73.46,26.96 v1(74.5,26.96) C98.1@75.5,26.96 L27.2@75.5,27.9
AUD_CLK: R1.2 U17.21 | length 42.5
  Layer 10 w0.125: v1(46.125,49) 46.125,47.125 46.75,46.5 47.125,46.5 47.5,46.125 47.5,38.375 48.375,37.5 48.375,33 50.875,30.5 51.5,30.5 54.75,27.25 57.375,27.25 57.875,27.75 59,27.75 60.375,29.125 63.625,29.125 63.875,29.375 64.5,29.375 65.5,28.375 v1(65.5,27.625)
  Bottom Layer w0.125: v1(46.125,49) 47.02,49.895 R1.2@47.02,50.5 ; v1(65.5,27.625) 66.125,27 66.5,27 66.75,26.75 U17.21@67.05,26.75
AUD_HP_DET: D9.2 J22.5 R93.1 U1.J24 | length 62.1
  Top Layer w0.125: J22.5@67.725,6.125 v1(69,6.125) ; D9.2@70.425,13.25 v1(71,13.25) ; v1(93.5,45.625) U1.J24@93.5,46.5
  Layer 5 w0.125: v1(71,13.25) 71,13.375 74.25,16.625 74.25,18.75 73.75,19.25 73.75,20.375 74.25,20.875 74.25,22.125 v1(74.625,22.5)
  Layer 10 w0.125: v1(74.625,22.5) 79.25,22.5 79.75,23 81.25,23 81.625,22.625 82.875,22.625 84.25,24 88.375,24 93,28.625 93,32.25 94.875,34.125 94.875,44.25 v1(93.5,45.625)
  Layer 3 w0.125: v1(69,6.125) 71,8.125 v1(71,13.25)
  Bottom Layer w0.125: R93.1@73.98,22.5 v1(74.625,22.5)
AUD_I2C_SCL: R114.2 U17.29 | length 32.6
  Layer 10 w0.125: v1(47.5,31.375) 48.25,30.625 49.875,30.625 52.875,27.625 53.375,27.625 54.5,26.5 56,26.5 56.337,26.163 61.296,26.163 61.458,26 65,26 66.25,27.25 69.25,27.25 71.25,29.25 v1(71.25,30.25)
  Bottom Layer w0.125: R114.2@47.02,30.625 47.5,31.105 v1(47.5,31.375) ; U17.29@69.75,28.95 69.75,30.375 70.125,30.75 70.75,30.75 v1(71.25,30.25)
AUD_I2C_SDA: R115.2 U17.27 | length 57
  Layer 10 w0.125: v1(46.75,46) 47,45.75 47,43.5 46.125,42.625 46.125,40.75 46.875,40 46.875,38 47.75,37.125 47.75,33.25 46.5,32 46.5,31.25 47.375,30.375 49.625,30.375 52.25,27.75 52.25,27.25 53.25,26.25 54.25,26.25 55.875,24.625 61.25,24.625 62.375,25.75 65.104,25.75 65.979,26.625 72.875,26.625 73.375,27.125 73.375,29 v1(72.625,29.75)
  Bottom Layer w0.125: v1(46.75,46) R115.2@47.48,46 ; U17.27@68.75,28.95 68.75,30.25 69.5,31 71.375,31 v1(72.625,29.75)
AUD_RXD: U1.M5 U17.25 | length 18.4
  Top Layer w0.125: U1.M5@55.5,40.5 v1(56.25,40.125)
  Layer 10 w0.125: v1(56.25,40.125) 57,39.375 57.25,39.375 63.25,33.375 63.25,32.625 64.625,31.25 67,31.25 67.75,30.5 v1(67.75,29.875) v1@67.75,29.75
  Bottom Layer w0.125: U17.25@67.75,28.95 v1(67.75,29.875)
AUD_TXC: U1.B7 U17.24 | length 37
  Top Layer w0.125: U1.B7@59.5,60.5 v1(60.375,60.375)
  Layer 8 w0.125: v1(60.375,60.375) 61.375,60.375 61.75,60 61.75,55 62.337,54.413 62.337,51.204 62.625,50.917 62.625,31.875 65.75,28.75 v1(66.375,28.75)
  Bottom Layer w0.125: v1(66.375,28.75) 66.375,28.375 66.5,28.25 U17.24@67.05,28.25
AUD_TXD: U1.C7 U17.26 | length 35.6
  Top Layer w0.125: U1.C7@59.5,58.5 v1(60.75,58.125)
  Layer 5 w0.125: v1(60.75,58.125) 61.125,58.125 63.75,55.5 63.75,31.625 64.375,31 67.5,31 v1(68.25,30.25)
  Bottom Layer w0.125: U17.26@68.25,28.95 v1(68.25,30.25)
AUD_TXFS: U1.C5 U17.23 | length 38.7
  Top Layer w0.125: U1.C5@55.5,58.5 56.375,59.125
  Layer 5 w0.125: v1(56.625,59.125) 59,59.125 61.75,56.375 61.75,51.75 62.75,50.75 62.75,36 63.25,35.5 63.25,31.375 65.5,29.125 65.5,28.375 v1(66.125,27.75)
  Bottom Layer w0.125: v1(66.125,27.75) U17.23@67.05,27.75
BOOT_CFG_1_4: R18.1 U1.W24 | length 5.4
  Top Layer w0.125: U1.W24@93.5,26.5 v1(94.25,26.875)
  Bottom Layer w0.125: R18.1@93.98,30.5 93.5,30.02 93.5,29.375 94.75,28.125 94.75,27.375 v1(94.25,26.875)
BOOT_CFG_1_5: J5.1 R10.1 U1.AA19 U4.1 | length 100.6
  Top Layer w0.125: v1(82.75,23.25) U1.AA19@83.5,22.5
  Layer 8 w0.125: v1(80.5,19.125) 81,19.625 81,21.5 v1(82.75,23.25)
  Layer 5 w0.125: J5.1@17.625,47 19.125,45.5 19.125,33.125 23.125,29.125 23.125,20.375 25.25,18.25 30.25,18.25 30.875,17.625 44.5,17.625 45.25,16.875 46.625,16.875 47.875,15.625 v1(47.875,14.25)
  Layer 10 w0.125: v1(47.875,14.25) 58.25,14.25 58.875,14.875 76.125,14.875 77.375,16.125 77.375,18 78.5,19.125 v1(80.5,19.125)
  Bottom Layer w0.125: U4.1@79.6,19.15 v1@80.475,19.15 ; v1(80.5,19.125) R10.1@81.355,19.125
BOOT_CFG_1_6: J4.1 R9.1 U1.U23 U2.1 | length 114.5
  Top Layer w0.125: v1(90.75,29.75) U1.U23@91.5,30.5
  Layer 5 w0.125: J4.1@15.125,47 13.875,45.75 13.875,42.875 14.875,41.875 16.125,41.875 17,41 17,25.125 24.125,18 29.875,18 30.5,17.375 44,17.375 45.875,15.5 v1(46.625,15.5) ; v1(80.5,22.125) 83.5,22.125 84.75,23.375 87.75,23.375 90.75,26.375 v1(90.75,29.75)
  Layer 10 w0.125: v1(46.625,15.5) 46.875,15.75 57.625,15.75 58.125,15.25 75.75,15.25 76.75,16.25 76.75,17.75 79.375,20.375 79.375,21 v1(80.5,22.125)
  Bottom Layer w0.125: U2.1@79.6,22.15 v1@80.475,22.15 ; v1(80.5,22.125) R9.1@81.395,22.125
BOOT_CFG_1_7: R19.1 U1.Y21 | length 9.4
  Top Layer w0.125: v1(86.75,25.25) U1.Y21@87.5,24.5
  Layer 10 w0.125: v1(84.375,31.25) 86.125,29.5 86.125,27.125 85.875,26.875 85.875,26.125 v1(86.75,25.25)
  Bottom Layer w0.125: R19.1@83.855,30.5 83.855,31.105 84,31.25 v1(84.375,31.25)
BOOT_CFG_2_5: R16.1 U1.V20 | length 2.1
  Top Layer w0.125: v1(85,29.5) U1.V20@85.5,28.5
  Bottom Layer w0.125: v1(85,29.5) R16.1@85,30.48
BOOT_CFG_2_6: R17.1 U1.W21 | length 6.9
  Top Layer w0.125: v1(86.875,25.875) U1.W21@87.5,26.5
  Layer 8 w0.125: v1(86.875,25.875) 87.375,26.375 87.375,27.625 88.625,28.875 v1(88.625,30.5)
  Bottom Layer w0.125: R17.1@87.98,30.5 v1(88.625,30.5)
BOOT_MODE0: R24.1 R28.2 U1.E17 | length 4.7
  Top Layer w0.125: U1.E17@79.5,54.5 v1(80.375,54.5)
  Layer 10 w0.125: v1(80.375,54.5) 81,55.125 81,55.875 v1(80.375,56.5)
  Bottom Layer w0.125: v1(80.375,54.5) R28.2@81.02,54.5 ; v1(80.375,56.5) R24.1@81.02,56.5
BOOT_MODE1: R25.1 R29.2 U1.F15 | length 8.7
  Top Layer w0.125: U1.F15@75.5,52.5 v1(76.125,53.125)
  Layer 5 w0.125: v1(76.125,53.125) 76.75,52.5 v1(80.375,52.5) v1(80.375,50.5)
  Bottom Layer w0.125: v1(80.375,50.5) R29.2@81.02,50.5 ; v1(80.375,52.5) R25.1@81.02,52.5
BT_DISABLE_N: R4.2 U1.H3 | length 10.5
  Top Layer w0.125: v1(50.675,48.5) U1.H3@51.5,48.5
  Layer 8 w0.125: v1(50.5,56.5) 51.125,55.875 51.125,48.95 v1(50.675,48.5)
  Bottom Layer w0.125: v1(50.5,56.5) 50.98,56.02 R4.2@51.5,56.02
CAN1_H: J27.2 R104.2 U18.7 | length 9.7
  Bottom Layer w0.125: R104.2@91.98,56.5 91.98,59.48 92.24,59.74 U18.7@93.325,59.74 95.24,59.74 96.875,61.375 J27.2@97.875,61.375
CAN1_L: J27.1 R104.1 U18.6 | length 11.3
  Bottom Layer w0.125: R104.1@91.02,56.5 91.02,59.77 92.26,61.01 U18.6@93.325,61.01 95.01,61.01 96.625,62.625 J27.1@97.875,62.625
CAN1_RXD: U1.F3 U18.4 | length 43.6
  Top Layer w0.125: U1.F3@51.5,52.5 v1(52.25,52.875)
  Layer 10 w0.125: v1(52.25,52.875) 53.125,52 54.5,52 55.125,52.625 65.125,52.625 68.375,55.875 68.375,56.125 72.75,60.5 87.375,60.5 v1(89.125,62.25)
  Bottom Layer w0.125: U18.4@87.955,62.25 v1(89.125,62.25)
CAN1_STBY: U1.G3 U18.8 | length 48.5
  Top Layer w0.125: U1.G3@51.5,50.5 v1(52.325,50.3)
  Layer 10 w0.125: v1(52.325,50.3) 52.75,50.3 52.925,50.125 57,50.125 57.25,49.875 61.875,49.875 64.375,52.375 65.25,52.375 68.625,55.75 68.625,56 71.25,58.625 85.375,58.625 85.75,59 94,59 v1(94.5,58.5)
  Bottom Layer w0.125: U18.8@93.355,58.5 v1(94.5,58.5)
CAN1_TXD: U1.P3 U18.1 | length 49.1
  Top Layer w0.125: U1.P3@51.5,36.5 v1(52.375,36.875)
  Layer 10 w0.125: v1(52.375,36.875) 54.75,39.25 54.75,45.25 58,48.5 60.875,48.5 64.5,52.125 65.375,52.125 68.875,55.625 68.875,55.875 71.375,58.375 85.875,58.375 86,58.5 v1(86.5,58.5)
  Bottom Layer w0.125: v1(86.5,58.5) U18.1@87.895,58.5
CAN2_H: J27.5 R116.2 U19.7 | length 10.5
  Bottom Layer w0.125: U19.7@93.2,51.865 94.49,51.865 95.125,52.5 95.125,56.5 ; R116.2@93.98,56.5 95.125,56.5 ; J27.5@97.875,57.625 96.25,57.625 95.125,56.5
CAN2_L: J27.4 R116.1 U19.6 | length 10.8
  Bottom Layer w0.125: U19.6@93.2,53.135 94.135,53.135 94.375,53.375 94.375,54.875 93.25,56 93.25,57 93.75,57.5 95,57.5 96.375,58.875 J27.4@97.875,58.875
CAN2_RXD: U1.D21 U19.4 | length 3.3
  Top Layer w0.125: v1(86.625,55.875) U1.D21@87.5,56.5
  Bottom Layer w0.125: v1(86.625,55.875) 87,55.875 87.8,55.075 U19.4@87.8,54.405
CAN2_STBY: U1.R3 U19.8 | length 74.6
  Top Layer w0.125: v1(51.5,33.625) U1.R3@51.5,34.5
  Layer 8 w0.125: v1(67,30.5) 67,29.75 68.25,28.5 71.75,28.5 72.125,28.125 73.125,28.125 75,30 84.125,30 85,30.875 85,44.875 84.212,45.663 84.212,47.788 83.25,48.75 83.25,50.75 82.5,51.5 v1(82.125,51.5)
  Layer 10 w0.125: v1(51.5,33.625) 55.25,33.625 55.5,33.875 56,33.875 59.125,30.75 65.5,30.75 65.75,31 66.625,31 67,30.625 v1(67,30.5) ; v1(82.125,51.5) 84.5,51.5 84.625,51.625 86.25,51.625 87.25,50.625 v1(94.375,50.625)
  Bottom Layer w0.125: U19.8@93.23,50.625 v1(94.375,50.625)
CAN2_TXD: U1.F20 U19.1 | length 3.5
  Top Layer w0.125: U1.F20@85.5,52.5 85.5,51.75 v1(86.625,50.625)
  Bottom Layer w0.125: v1(86.625,50.625) U19.1@87.77,50.625
CLK1_N: C31.1 U1.B18 | length 32.8
  Top Layer w0.175: v1(80.875,61.125) U1.B18@81.5,60.5
  Layer 8 w0.119: v1(56.825,53.375) 56.622,53.578 56.622,55.422 57.598,56.398 57.669,56.469 57.669,58.594 61.575,62.5 77.28,62.5 78.402,61.378 80.622,61.378 v1(80.875,61.125)
  Bottom Layer w0.175: v1(56.825,53.375) C31.1@57.5,52.96
CLK1_P: C32.1 U1.A18 | length 33.2
  Top Layer w0.175: v1(80.875,61.875) U1.A18@81.5,62.5
  Layer 8 w0.119: v1(56.175,53.375) 56.175,53.425 56.378,53.628 56.378,55.523 57.425,56.57 57.425,58.695 61.474,62.744 77.381,62.744 78.503,61.622 80.622,61.622 v1(80.875,61.875)
  Bottom Layer w0.175: C32.1@55.5,52.96 v1(56.175,53.375)
CONSOLE_RX: J9.2 U8.4 | length 19.2
  Top Layer w0.125: v1(22,52.75) U8.4@22,55.247
  Layer 10 w0.125: J9.2@6,51.125 15.625,51.125 15.875,51.375 18.25,51.375 19.625,52.75 v1(22,52.75)
CONSOLE_TX: J9.1 U8.9 | length 23.2
  Top Layer w0.125: v1(25.25,52.25) U8.9@25.25,55.247
  Layer 10 w0.125: J9.1@6,49.875 6.875,49.875 7.125,50.125 17.625,50.125 19.75,52.25 v1(25.25,52.25)
CSI0_DAT12: J17.2 U1.L5 | length 34.2
  Top Layer w0.125: J17.2@48.75,66.8 48.75,66 53.5,61.25 55.75,61.25 56.288,60.712 56.712,60.712 57.25,61.25 57.75,61.25 58.5,60.5 58.5,50.25 59.875,48.875 59.875,45.875 56.5,42.5 U1.L5@55.5,42.5
CSI0_DAT13: J17.3 U1.C6 | length 15.8
  Top Layer w0.125: J17.3@48.25,66.8 48.25,63.25 52.625,58.875 52.625,58.25 53.125,57.75 56.75,57.75 U1.C6@57.5,58.5
CSI0_DAT14: J17.4 U1.B6 | length 19.8
  Top Layer w0.125: J17.4@47.75,66.8 47.75,63.375 52.25,58.875 52.25,58 52.75,57.5 57.625,57.5 58.25,58.125 58.25,59.75 U1.B6@57.5,60.5
CSI0_DAT15: J17.5 U1.E6 | length 20.6
  Top Layer w0.125: J17.5@47.25,66.8 47.25,66.083 47.5,65.833 47.5,63.125 47.75,62.875 47.75,57.25 49.25,55.75 56.25,55.75 U1.E6@57.5,54.5
CSI0_DAT16: J17.6 U1.H6 | length 27.5
  Top Layer w0.125: J17.6@46.75,66.8 46.75,66.083 46.587,65.921 46.587,65.413 47,65 47,62.625 47.25,62.375 47.25,57 49,55.25 53.75,55.25 55.212,53.788 57.212,53.788 58.25,52.75 58.25,50 57.5,49.25 U1.H6@57.5,48.5
CSI0_DAT17: J17.7 U1.A7 | length 20.2
  Top Layer w0.125: J17.7@46.25,66.8 46.25,68.375 46.625,68.75 50.875,68.75 52.625,67 52.625,64.25 55.125,61.75 55.792,61.75 56.329,62.288 56.712,62.288 57.25,61.75 57.75,61.75 58.5,62.5 U1.A7@59.5,62.5
CSI0_DAT18: J17.8 U1.F6 | length 24.6
  Top Layer w0.125: J17.8@45.75,66.8 45.75,65.375 46.75,64.375 46.75,62.375 47,62.125 47,56.875 48.625,55.25 48.625,54.125 49.25,53.5 52.375,53.5 52.75,53.125 52.75,52.125 53.075,51.8 55.8,51.8 56.5,52.5 U1.F6@57.5,52.5
CSI0_DAT19: J17.9 U1.G6 | length 25.5
  Top Layer w0.125: J17.9@45.25,66.8 45.25,66.125 45.5,65.875 45.5,65.125 46.5,64.125 46.5,62.125 46.75,61.875 46.75,56.75 48.375,55.125 48.375,52.5 49.25,51.625 52.75,51.625 52.875,51.5 55.5,51.5 56.5,50.5 U1.G6@57.5,50.5
CSI0_GPIO: J17.15 U1.E5 | length 24.4
  Top Layer w0.125: J17.15@42.25,66.8 v1(42.25,67.75) ; v1(47,65.75) 47.25,65.5 47.25,62.875 47.5,62.625 47.5,57.125 49.125,55.5 54.5,55.5 U1.E5@55.5,54.5
  Layer 10 w0.125: v1(42.25,67.75) 43.625,66.375 46.375,66.375 v1(47,65.75)
CSI0_HSYNC: J17.13 U1.A5 | length 18.1
  Top Layer w0.125: J17.13@43.25,66.8 43.25,68.625 43.625,69 50.979,69 52.875,67.104 52.875,65.125 U1.A5@55.5,62.5
CSI0_I2C_SCL: J17.18 R108.2 | length 36.9
  Top Layer w0.125: J17.18@40.75,66.8 40.75,65.665 41.54,64.875 43,64.875 44.5,63.375 44.5,51.625 45.625,50.5 45.625,41.125 46.5,40.25 46.5,34.625 v1(46.125,34.25)
  Bottom Layer w0.125: v1(46.125,34.25) 46.895,34.25 R108.2@47.02,34.375
CSI0_I2C_SDA: J17.19 R111.2 | length 28.8
  Top Layer w0.125: J17.19@40.25,66.8 40.25,65.75 41.375,64.625 42.75,64.625 44.25,63.125 44.25,51.375 45.375,50.25 45.375,46.375 v1(45,46)
  Bottom Layer w0.125: v1(45,46) 45.5,46.5 49.02,46.5 R111.2@49.5,46.02
CSI0_MCLK: J17.11 R3.2 | length 16.7
  Top Layer w0.125: J17.11@44.25,66.8 44.25,65.5 45.75,64 45.75,52.625 v1(45.5,52.375)
  Bottom Layer w0.125: v1(45.5,52.375) R3.2@47.02,52.375
CSI0_PIXCLK: J17.12 U1.G5 | length 26.5
  Top Layer w0.125: J17.12@43.75,66.8 43.75,65.375 45.25,63.875 45.25,53.125 45,52.875 45,52.25 46,51.25 54.75,51.25 U1.G5@55.5,50.5
CSI0_RESET_N: J17.16 U1.AA13 | length 71.9
  Top Layer w0.125: J17.16@41.75,66.8 v1(41.75,68.25) ; v1(70.75,22.875) U1.AA13@71.5,22.5
  Layer 5 w0.125: v1(41.75,68.25) 42.25,68.75 51.25,68.75 52,68 52,63.875 55.75,60.125 55.75,58.75 56.146,58.354 57.75,58.354 59.218,56.886 60.114,56.886 61.25,55.75 61.25,51.521 62.25,50.521 62.25,35.75 62.75,35.25 62.75,31.164 63.75,30.164 63.75,26 63.625,25.875 63.625,23 64.125,22.5 66.25,22.5 66.625,22.875 v1(70.75,22.875)
CSI0_VSYNC: J17.14 U1.J5 | length 30
  Top Layer w0.125: J17.14@42.75,66.8 42.75,65.625 44.75,63.625 44.75,51.875 45.875,50.75 45.875,50.125 46.5,49.5 54,49.5 54.5,49 54.5,47.5 U1.J5@55.5,46.5
CSI1_D12: J33.1 U1.AC17 | length 35.8
  Top Layer w0.125: v1(78.5,18.5) U1.AC17@79.5,18.5
  Layer 5 w0.125: v1(94.125,15.375) 94.625,15.375 96.25,17 96.25,29.5 J33.1@97.875,31.125
  Layer 10 w0.125: v1(78.5,18.5) 79.5,17.5 79.5,17 81.125,15.375 v1(94.125,15.375)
